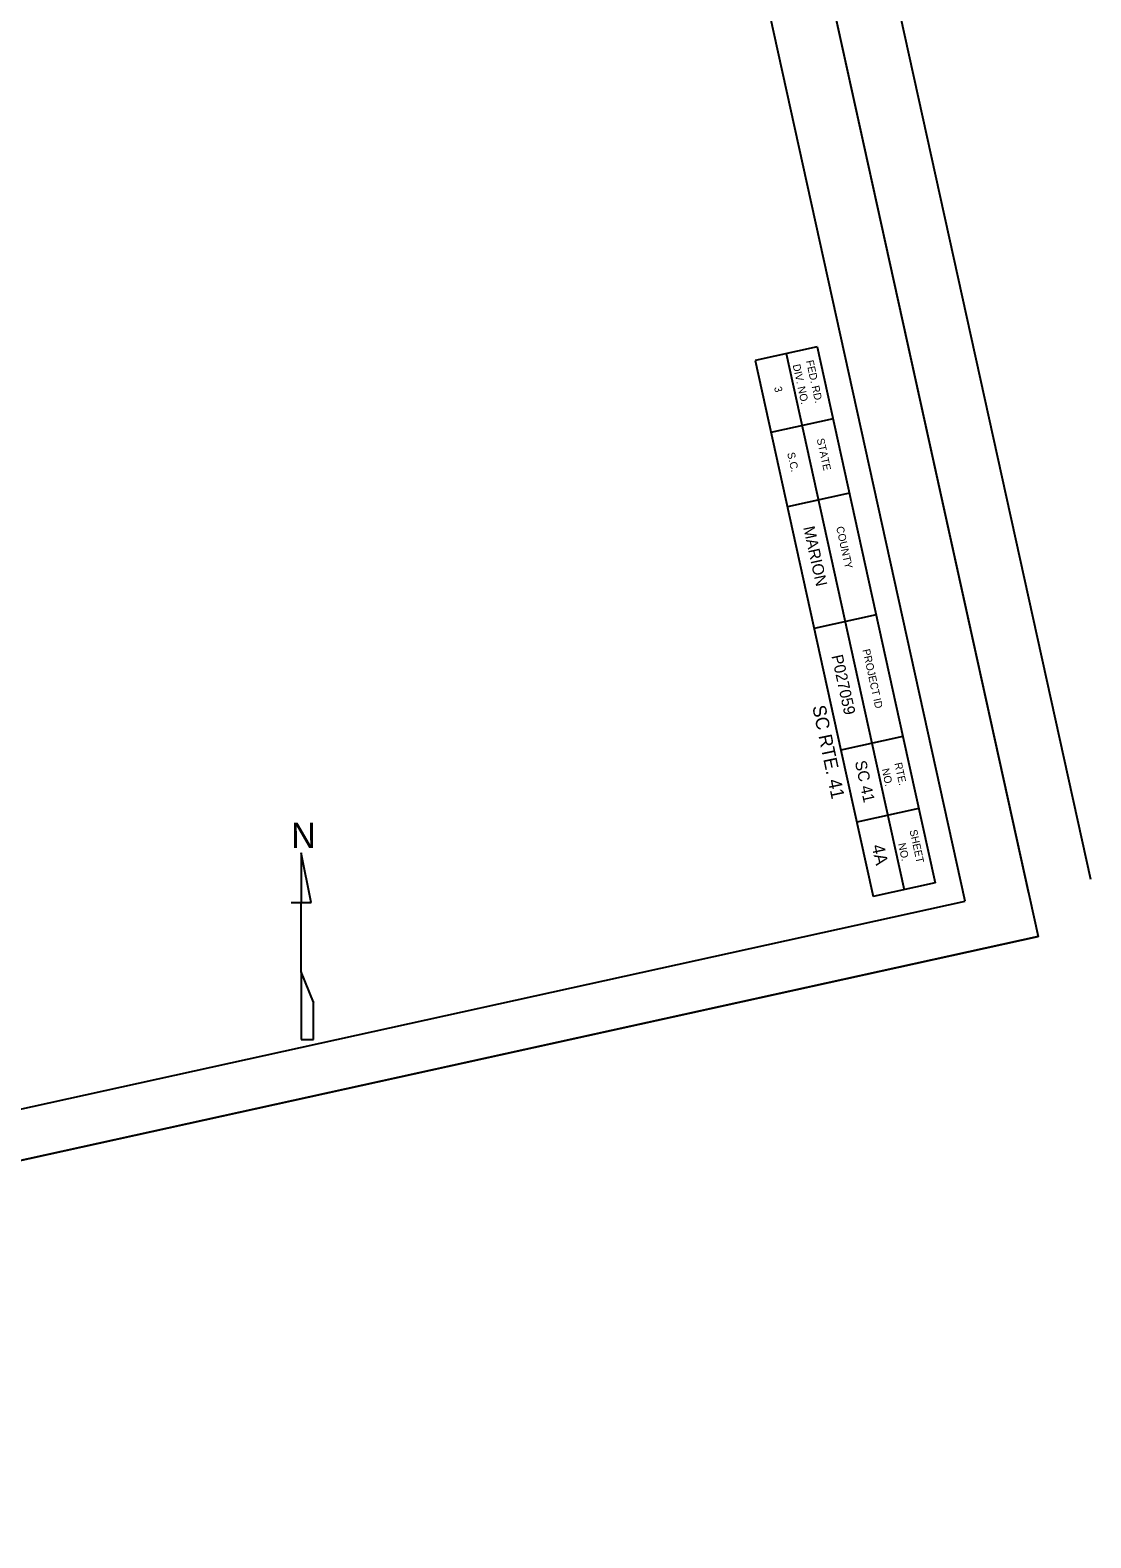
# Model space of a CAD drawing. Extents: x 2521558 to 2525396, y 882711 to 887632.
# Drawn here: x 2524562 to 2525396, y 882849 to 884035 of the extents above; entities that cross this region are included whole.
import ezdxf

# ---------------------------------------------------------------- set-up
doc = ezdxf.new("R2010")
doc.units = 0
for name, color, linetype in [('RD_EX_Misc', 7, 'Continuous'), ('RD_SHT_Bndy', 7, 'Continuous'), ('RD_SHT_IplotShp', 7, 'Continuous'), ('RD_SHT_Snap', 7, 'Continuous'), ('RD_SHT_TX', 7, 'Continuous'), ('RD_TX_TypSect', 7, 'Continuous')]:
    doc.layers.add(name, color=color, linetype=linetype)

msp = doc.modelspace()

# ---------------------------------------------------------------- linework, layer by layer
at = {"layer": 'RD_EX_Misc'}
for p, q in [((2524782.6, 883348.9), (2524774.7, 883388.1)), ((2524774.7, 883388.1), (2524774.7, 883388.1)), ((2524774.7, 883388.1), (2524774.7, 883348.9)), ((2524766.9, 883348.9), (2524774.7, 883348.9)), ((2524774.7, 883294.5), (2524774.7, 883348.9)), ((2524774.7, 883348.9), (2524782.6, 883348.9)), ((2524782.6, 883348.9), (2524782.6, 883349.4)), ((2524784.5, 883270.5), (2524774.7, 883294.5)), ((2524774.7, 883294.5), (2524774.7, 883241.1)), ((2524784.5, 883241.1), (2524784.5, 883270.8)), ((2524784.5, 883270.8), (2524784.5, 883270.5)), ((2524774.7, 883241.1), (2524784.5, 883241.1))]:
    msp.add_line(p, q, dxfattribs=at)
at = {"layer": 'RD_SHT_Bndy'}
for p, q in [((2525395.7, 883367), (2524638.7, 886804.6)), ((2525346.9, 883356.2), (2524589.9, 886793.9)), ((2525297, 883350.2), (2524576.6, 886621.8)), ((2525180.5, 883786.3), (2525131.7, 883775.6)), ((2525131.7, 883775.6), (2525199.2, 883468.9)), ((2525156.1, 883780.9), (2525223.6, 883474.3)), ((2525180.5, 883786.3), (2525248, 883479.7)), ((2525193, 883729.7), (2525144.2, 883718.9)), ((2525205.9, 883671.1), (2525157.1, 883660.3)), ((2525227, 883575.4), (2525178.1, 883564.6)), ((2525248, 883479.7), (2525199.2, 883468.9)), ((2525248, 883479.7), (2525273.4, 883364.4)), ((2525199.2, 883468.9), (2525224.6, 883353.7)), ((2525223.6, 883474.3), (2525249, 883359)), ((2525260.5, 883423), (2525211.7, 883412.3)), ((2525273.4, 883364.4), (2525224.6, 883353.7)), ((2523246.2, 882898.6), (2525297, 883350.2))]:
    msp.add_line(p, q, dxfattribs=at)
at = {"layer": 'RD_SHT_IplotShp'}
msp.add_lwpolyline([(2524581.9, 886830.2), (2525354.4, 883322.2), (2523205.9, 882849.1), (2522433.4, 886357.1)], close=True, dxfattribs=at)
at = {"layer": 'RD_SHT_Snap'}
msp.add_line((2523205.9, 882849.1), (2525354.4, 883322.2), dxfattribs=at)

# ---------------------------------------------------------------- texts
at = {"layer": 'RD_EX_Misc'}
msp.add_text('N', height=20, dxfattribs=at).set_placement((2524766.9, 883391.8))
at = {"layer": 'RD_SHT_TX'}
for s, height, p in [('FED. RD.', 6, (2525171.7, 883775.1)), ('DIV. NO.', 6, (2525161.2, 883771.9)), ('3', 6, (2525146.6, 883754.3)), ('STATE', 6, (2525180.1, 883713.6)), ('S.C.', 6, (2525156.9, 883702.6)), ('MARION', 9, (2525169.5, 883644.1)), ('COUNTY', 6, (2525195.4, 883644.3)), ('P027059', 9, (2525191.7, 883543)), ('PROJECT ID', 6, (2525216.1, 883547.8)), ('SC 41', 9, (2525210.1, 883459.7)), ('RTE.', 6, (2525241.2, 883458.5)), ('NO.', 6, (2525231.2, 883453.9)), ('NO.', 6, (2525244.1, 883395.2)), ('SHEET', 6, (2525253.1, 883405.7)), ('4A', 10, (2525223.3, 883393.6))]:
    msp.add_text(s, height=height, rotation=282.4185, dxfattribs=at).set_placement(p)
at = {"layer": 'RD_TX_TypSect'}
msp.add_text('SC RTE. 41', height=10.5, rotation=281.9007, dxfattribs=at).set_placement((2525176.6, 883503.1))

doc.saveas('drawing.dxf')
